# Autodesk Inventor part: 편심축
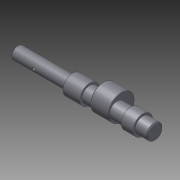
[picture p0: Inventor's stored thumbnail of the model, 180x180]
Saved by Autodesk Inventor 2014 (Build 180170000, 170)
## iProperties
Company: 한국ATC센터
Created: 2015-12
Part Number: 편심축
Document SubType Name: Modeling
Designer: mdu
Density: 7.86 g/cm^3
Mass: 222.98 g
Surface Area: 83.5889 cm^2
Volume: 28.3689 cm^3
Material: 강철, 연강
Appearance: 강철
Author: mdu
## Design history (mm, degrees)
sketch "스케치1"
  geometry: L1 (-86, 0)-(86, 0); L2 (-86, 0)-(-86, 6); L3 (-86, 6)-(-32, 6); L4 (-32, 6)-(-32, 9.5); L5 (-32, 9.5)-(-15.5, 9.5); L6 (-15.5, 9.5)-(-15.5, 7.5); L7 (-15.5, 7.5)-(48, 7.5); L8 (86, 6)-(86, 0); L9 (36, 7.5)-(36, 9.5); L10 (36, 9.5)-(24.5, 9.5); L11 (24.5, 9.5)-(24.5, 7.5); L12 (48, 7.5)-(48, 6); L13 (48, 6)-(86, 6); 2 further points
  constraints: 26 end point, 6 parallel, 6 perpendicular, 2 point on line, 1 coincident, 1 horizontal, 1 midpoint
  dimensions: "d1" = 12 diameter of L3 L1; "d2" = 15 diameter of L7 L1; "d4" = 16.5 distance of L4.end L5.end; "d5" = 19 diameter of L5 L1; "d24" = 11.5 distance of L9.end L10.end; "d25" = 19 diameter of L10 L1; "d27" = 40 distance between parallel lines of L11 L6; "d28" = 54 distance of L2.end L3.end; "d29" = 50 distance between parallel lines of L8 L9; "d41" = 38 distance between parallel lines of L8 L12; "d42" = 12 diameter of L13 L1
revolve "회전1" stored, may be unused: angle "d6" = 90 deg
node "작업 평면1"
sketch "스케치2"
  geometry: C1 r 7.5 at (0, 0) reference; C2 r 12.5 at (0, 4.5); 1 further point
  constraints: 1 centre point, 1 vertical alignment
  dimensions: "d8" = 4.5 distance of point (0, 0) C2.centre; "d9" = 25 diameter of C2
extrude "돌출1" join sketch "스케치2" distance "d10" = 18; taper "d11" = 0 deg
chamfer "모따기1" distance "d12" = 1; stored, may be unused: second distance "d13" = 2, angle "d14" = 45 deg
chamfer "모따기2" distance "d15" = 0.5; stored, may be unused: second distance "d16" = 2, angle "d17" = 45 deg
node "작업 평면2"
sketch "스케치3"
  geometry: L1 (4, -2)-(18, -2); L2 (18, 2)-(4, 2); L3 (27, 5)-(27, -5) reference; A1 r 2 centre (18, 0) between (18, -2) and (18, 2); A2 r 2 centre (4, 0) between (4, 2) and (4, -2); 2 further points
  constraints: 4 end point, 4 point on circle, 4 tangent, 2 centre point, 1 horizontal, 1 horizontal alignment, 1 midpoint, 1 parallel
  dimensions: "d18" = 7 distance edge to line of A1 L3; "d19" = 4 distance between parallel lines of L2 L1; "d20" = 18 dimension on A1 A2
extrude "돌출2" cut sketch "스케치3" distance "d21" = 2.5; taper "d22" = 0 deg
revolve "회전2" stored, may be unused: angle "d26" = 90 deg
node "작업 평면3"
sketch "스케치4"
  geometry: L1 (44, 5)-(44, -5) reference; 2 further points
  constraints: 1 horizontal alignment
  dimensions: "d30" = 12 distance from line of point (32, 0) L1
hole "구멍1" sketch "스케치4" at (32, 0) diameter "d31" = 6; stored, may be unused: countersink angle "d35" = 90 deg, drill point angle "d37" = 118 deg; dims "d32" = 6, "d33" = 14, "d34" = 3, "d36" = 8
node "작업 평면4"
sketch "스케치5"
  geometry: C1 r 3 at (32, 0) reference; C2 r 8 at (32, 0); 2 further points
  constraints: 1 centre point, 1 coincident, 1 other
  dimensions: "d38" = 16 diameter of C2
extrude "돌출3" cut sketch "스케치5" distance "d39" = 3; taper "d40" = 0 deg
sketch "스케치6"
  geometry: L1 (-85, -6)-(-32, -6) reference; L2 (-86, -5)-(-86, 5) reference; L3 (-85, 6)-(-32, 6) reference; L4 (-64, 6)-(-64, -6); L5 (-64, -6)-(-62.5, -6); L6 (-64, -4.5)-(-62.5, -6); L7 (-64, -6)-(-64, -4.5); 2 further points
  constraints: 8 end point, 4 point on line, 2 perpendicular, 1 coincident
  dimensions: "d43" = 22 distance between parallel lines of L4 L2; "d44" = 45 deg angle of L6 L7; "d45" = 3 diameter of L5.end L4
revolve "회전3" stored, may be unused: angle "d46" = 90 deg
node "작업점1"
chamfer "모따기3" distance "d47" = 0.5; stored, may be unused: second distance "d48" = 2, angle "d49" = 45 deg
sketch "스케치7"
  geometry: C1 r 7.5 at (0, 0) reference; 1 further point
extrude "돌출4" cut sketch "스케치7" stored distance "d50" = 10; taper "d51" = 0 deg
chamfer "모따기4" distance "d52" = 1; stored, may be unused: second distance "d53" = 2, angle "d54" = 45 deg
node "작업 평면5"
hole "구멍2" diameter "d63" = 4.917; stored, may be unused: countersink angle "d67" = 90 deg, drill point angle "d69" = 118 deg; dims "d64" = 12, "d65" = 4, "d66" = 2, "d68" = 15, "d72" = 10, "d73" = 10
node "솔리드1"
node "투영된 루프1"
other parameters: "d7" = 8.5
